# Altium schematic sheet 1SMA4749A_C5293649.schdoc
size 127 x 101 mm
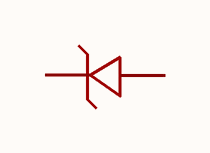
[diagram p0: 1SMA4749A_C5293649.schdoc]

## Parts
D?  1sma4749a_c5293649  [SMA_L4.4-W2.8-LS5.4-RD]  (value not drawn)

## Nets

Not connected (* = marked no-connect by the designer): D? 1(C) 2(A)

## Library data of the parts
D? = 1sma4749a_c5293649: 稳压值(标称值):24V;稳压值(范围):-;耗散功率(Pd):1W;; Manufacturer: CJ(江苏长电/长晶); AddInBom: yes; ModelId: 4f1e9ef2303f48b48aa8ce0cacf8d7b1; ModelTransform: 204.724,102.362,0,0,0,0,0,0,0; Zener Voltage(Nom): 24V; Reverse Leakage Current (Ir): 100nA; Pd - Power Dissipation: 1W; Impedance(Zzt): 25Ω; Impedance(Zzk): 750Ω; Operating Junction Temperature Range: -55℃~+150℃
